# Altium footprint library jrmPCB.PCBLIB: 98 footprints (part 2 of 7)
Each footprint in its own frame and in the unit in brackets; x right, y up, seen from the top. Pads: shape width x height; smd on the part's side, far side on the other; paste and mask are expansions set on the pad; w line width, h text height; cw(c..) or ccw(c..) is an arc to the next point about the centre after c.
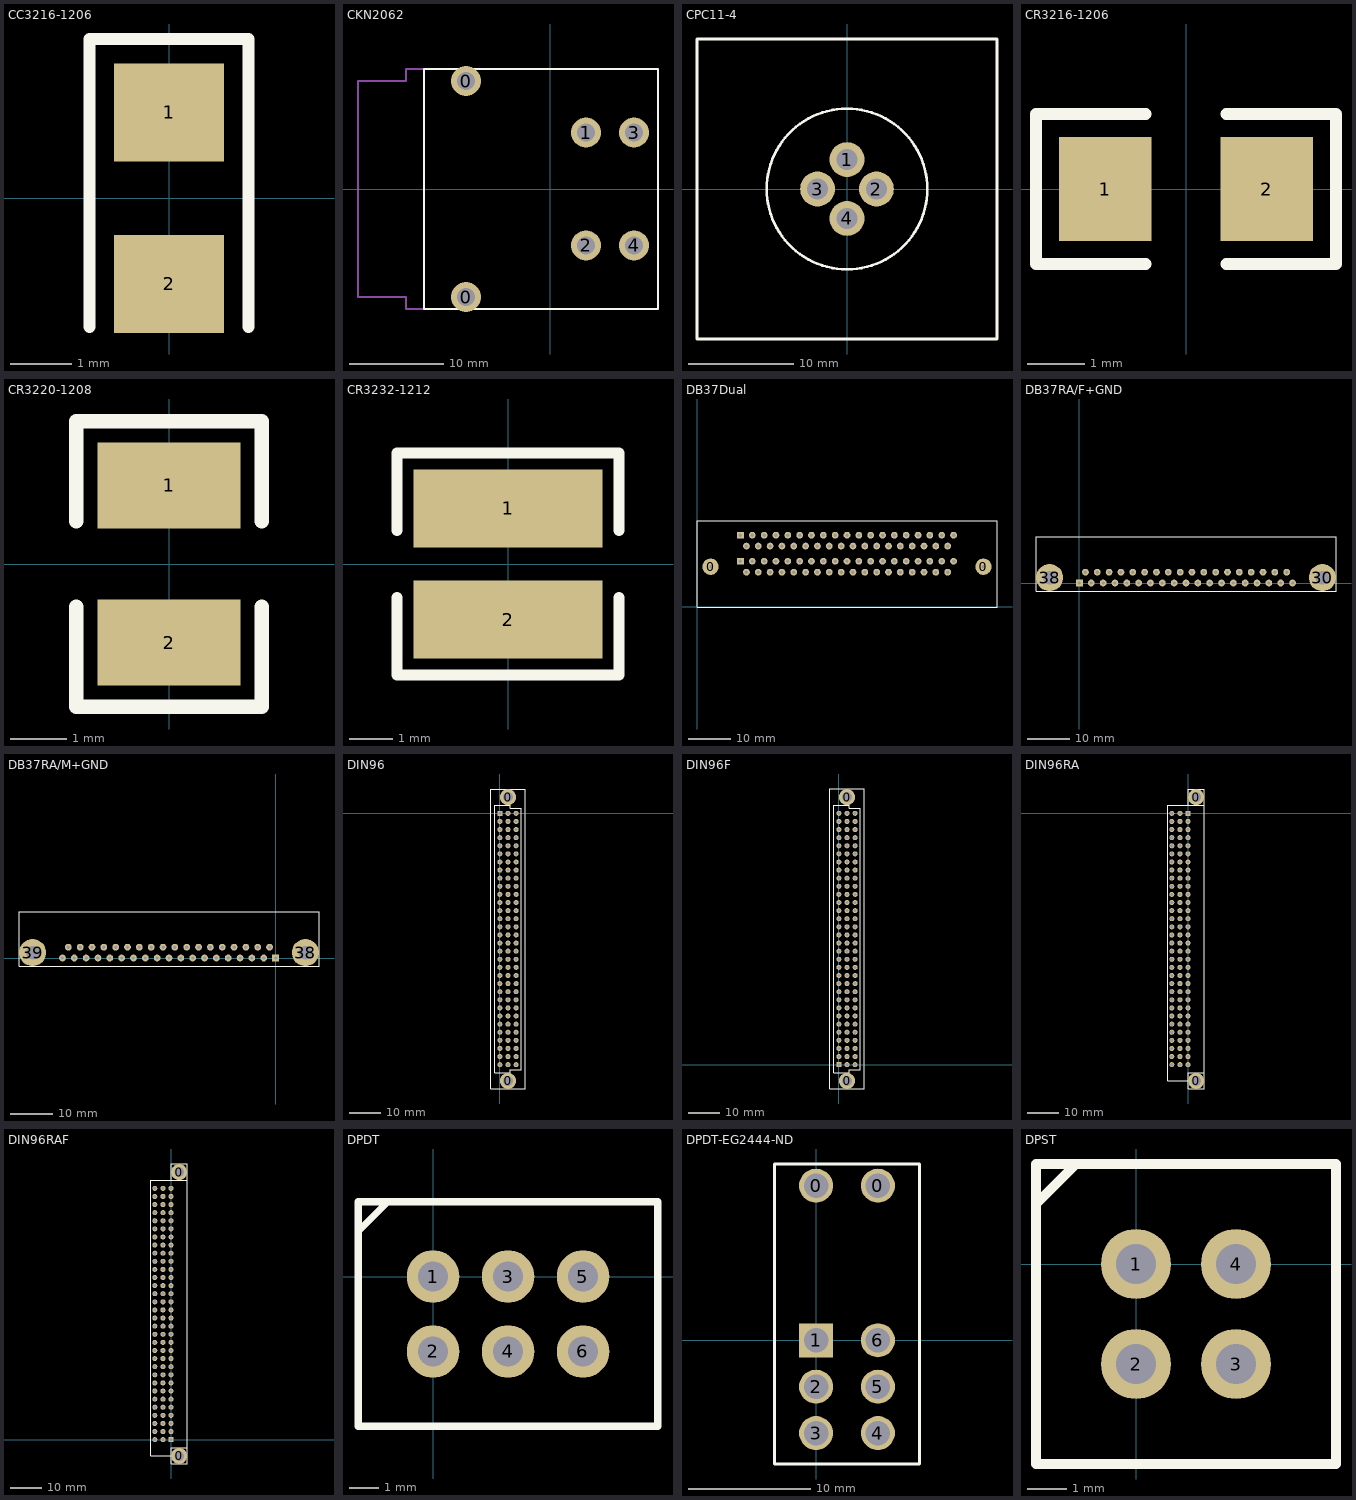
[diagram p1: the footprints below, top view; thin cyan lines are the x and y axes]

## CC3216-1206 [mm]
pads (2):
  rect 1.8x1.6 smd: 1(0,1.4) 2(0,-1.4)
Top Overlay:
  lines w0.2: -1.3,-2.1 -1.3,2.6 1.3,2.6 1.3,-2.1

## CKN2062 [mil] "DPST PCB Mount Rocker Switch"
pads (6):
  round 125 hole 75: 0(-350,-450) 0(-350,450) 1(150,235) 2(150,-235) 3(350,235) 4(350,-235)
Top Overlay:
  lines w10: -525,-500 -525,500 450,500 450,-500 -525,-500
Mechanical 2:
  lines w10: -525,-500 -600,-500 -600,-450 -800,-450 -800,450 -600,450 -600,500 -525,500

## CPC11-4 [mil] "PCB Mount for CPC 11-4 Solder Tab connector"
pads (4):
  round 130 hole 79: 1(0,110) 2(110,0) 3(-110,0) 4(0,-110)
Top Overlay:
  circle w10: c0,0 r300
  lines w10: -560,-560 560,-560 560,560 -560,560 -560,-560

## CR3216-1206 [mm]
pads (2):
  rect 1.6x1.8 smd: 1(-1.4,0) 2(1.4,0)
Top Overlay:
  lines w0.2: -0.7,-1.3 -2.6,-1.3 -2.6,1.3 -0.7,1.3 ; 0.7,-1.3 2.6,-1.3 2.6,1.3 0.7,1.3

## CR3220-1208 [mil]
pads (2):
  rect 100x60 smd: 1(0,55) 2(0,-55)
Top Overlay:
  lines w10: -65,-30 -65,-100 65,-100 65,-30 ; -65,30 -65,100 65,100 65,30

## CR3232-1212 [mil]
pads (2):
  rect 170x70 smd: 1(0,50) 2(0,-50)
Top Overlay:
  lines w10: -100,-30 -100,-100 100,-100 100,-30 ; -100,30 -100,100 100,100 100,30

## DB37Dual [mil]
pads (76):
  round 150 hole 32: 0(125,370) 0(2637,370)
  rect 62x62 hole 32: 1(400,420) 1(400,660.16)
  round 62 hole 32: 2(509,420) 2(509,660.16) 3(618,420) 3(618,660.16) 4(727,420) 4(727,660.16) 5(836,420) 5(836,660.16) 6(945,420) 6(945,660.16) 7(1054,420) 7(1054,660.16) 8(1163,420) 8(1163,660.16) 9(1272,420) 9(1272,660.16) 10(1381,420) 10(1381,660.16) 11(1490,420) 11(1490,660.16) 12(1599,420) 12(1599,660.16) 13(1708,420) 13(1708,660.16) 14(1817,420) 14(1817,660.16) 15(1926,420) 15(1926,660.16) 16(2035,420) 16(2035,660.16) 17(2144,420) 17(2144,660.16) 18(2253,420) 18(2253,660.16) 19(2362,420) 19(2362,660.16) 20(455,320) 20(455,560.16) 21(564,320) 21(564,560.16) 22(673,320) 22(673,560.16) 23(782,320) 23(782,560.16) 24(891,320) 24(891,560.16) 25(1000,320) 25(1000,560.16) 26(1109,320) 26(1109,560.16) 27(1218,320) 27(1218,560.16) 28(1327,320) 28(1327,560.16) 29(1436,320) 29(1436,560.16) 30(1545,320) 30(1545,560.16) 31(1654,320) 31(1654,560.16) 32(1763,320) 32(1763,560.16) 33(1872,320) 33(1872,560.16) 34(1981,320) 34(1981,560.16) 35(2090,320) 35(2090,560.16) 36(2199,320) 36(2199,560.16) 37(2308,320) 37(2308,560.16)
Top Overlay:
  lines w8: 0,795 2762,795 2762,-5
  lines w10: 0,795 0,-5 2762,-5

## DB37RA/F+GND [mil]
pads (39):
  rect 62x62 hole 32: 1(0,0)
  round 62 hole 32: 2(109,0) 3(218,0) 4(327,0) 5(436,0) 6(545,0) 7(654,0) 8(763,0) 9(872,0) 10(981,0) 11(1090,0) 12(1199,0) 13(1308,0) 14(1417,0) 15(1526,0) 16(1635,0) 17(1744,0) 18(1853,0) 19(1962,0) 20(55,100) 21(164,100) 22(273,100) 23(382,100) 24(491,100) 25(600,100) 26(709,100) 27(818,100) 28(927,100) 29(1036,100) 30(1145,100) 31(1254,100) 32(1363,100) 33(1472,100) 34(1581,100) 35(1690,100) 36(1799,100) 37(1908,100)
  round 250 hole 125: 30(2237,50) 38(-275,50)
Top Overlay:
  lines w8: -400,-75 2362,-75 2362,425
  lines w10: -400,-75 -400,425 2362,425

## DB37RA/M+GND [mil]
pads (39):
  rect 62x62 hole 32: 1(0,0)
  round 62 hole 32: 2(-109,0) 3(-218,0) 4(-327,0) 5(-436,0) 6(-545,0) 7(-654,0) 8(-763,0) 9(-872,0) 10(-981,0) 11(-1090,0) 12(-1199,0) 13(-1308,0) 14(-1417,0) 15(-1526,0) 16(-1635,0) 17(-1744,0) 18(-1853,0) 19(-1962,0) 20(-55,100) 21(-164,100) 22(-273,100) 23(-382,100) 24(-491,100) 25(-600,100) 26(-709,100) 27(-818,100) 28(-927,100) 29(-1036,100) 30(-1145,100) 31(-1254,100) 32(-1363,100) 33(-1472,100) 34(-1581,100) 35(-1690,100) 36(-1799,100) 37(-1908,100)
  round 250 hole 125: 38(275,50) 39(-2237,50)
Top Overlay:
  lines w8: -2362,425 -2362,-75 400,-75
  lines w10: -2362,425 400,425 400,-75

## DIN96 [mil]
pads (98):
  round 200 hole 125: 0(100,-3300) 0(100,200)
  rect 62x62 hole 40: 1A(0,0)
  round 62 hole 40: 1B(100,0) 1C(200,0) 2A(0,-100) 2B(100,-100) 2C(200,-100) 3A(0,-200) 3B(100,-200) 3C(200,-200) 4A(0,-300) 4B(100,-300) 4C(200,-300) 5A(0,-400) 5B(100,-400) 5C(200,-400) 6A(0,-500) 6B(100,-500) 6C(200,-500) 7A(0,-600) 7B(100,-600) 7C(200,-600) 8A(0,-700) 8B(100,-700) 8C(200,-700) 9A(0,-800) 9B(100,-800) 9C(200,-800) 10A(0,-900) 10B(100,-900) 10C(200,-900) 11A(0,-1000) 11B(100,-1000) 11C(200,-1000) 12A(0,-1100) 12B(100,-1100) 12C(200,-1100) 13A(0,-1200) 13B(100,-1200) 13C(200,-1200) 14A(0,-1300) 14B(100,-1300) 14C(200,-1300) 15A(0,-1400) 15B(100,-1400) 15C(200,-1400) 16A(0,-1500) 16B(100,-1500) 16C(200,-1500) 17A(0,-1600) 17B(100,-1600) 17C(200,-1600) 18A(0,-1700) 18B(100,-1700) 18C(200,-1700) 19A(0,-1800) 19B(100,-1800) 19C(200,-1800) 20A(0,-1900) 20B(100,-1900) 20C(200,-1900) 21A(0,-2000) 21B(100,-2000) 21C(200,-2000) 22A(0,-2100) 22B(100,-2100) 22C(200,-2100) 23A(0,-2200) 23B(100,-2200) 23C(200,-2200) 24A(0,-2300) 24B(100,-2300) 24C(200,-2300) 25A(0,-2400) 25B(100,-2400) 25C(200,-2400) 26A(0,-2500) 26B(100,-2500) 26C(200,-2500) 27A(0,-2600) 27B(100,-2600) 27C(200,-2600) 28A(0,-2700) 28B(100,-2700) 28C(200,-2700) 29A(0,-2800) 29B(100,-2800) 29C(200,-2800) 30A(0,-2900) 30B(100,-2900) 30C(200,-2900) 31A(0,-3000) 31B(100,-3000) 31C(200,-3000) 32A(0,-3100) 32B(100,-3100) 32C(200,-3100)
Top Overlay:
  lines w10: -110,-3400 310,-3400 310,300 -110,300 -110,-3400 ; -65,-3200 -65,100 130,100 130,65 265,65 265,-3165 130,-3165 130,-3200 -65,-3200

## DIN96F [mil]
pads (98):
  round 200 hole 125: 0(100,-200) 0(100,3300)
  rect 62x62 hole 40: 1A(0,0)
  round 62 hole 40: 1B(100,0) 1C(200,0) 2A(0,100) 2B(100,100) 2C(200,100) 3A(0,200) 3B(100,200) 3C(200,200) 4A(0,300) 4B(100,300) 4C(200,300) 5A(0,400) 5B(100,400) 5C(200,400) 6A(0,500) 6B(100,500) 6C(200,500) 7A(0,600) 7B(100,600) 7C(200,600) 8A(0,700) 8B(100,700) 8C(200,700) 9A(0,800) 9B(100,800) 9C(200,800) 10A(0,900) 10B(100,900) 10C(200,900) 11A(0,1000) 11B(100,1000) 11C(200,1000) 12A(0,1100) 12B(100,1100) 12C(200,1100) 13A(0,1200) 13B(100,1200) 13C(200,1200) 14A(0,1300) 14B(100,1300) 14C(200,1300) 15A(0,1400) 15B(100,1400) 15C(200,1400) 16A(0,1500) 16B(100,1500) 16C(200,1500) 17A(0,1600) 17B(100,1600) 17C(200,1600) 18A(0,1700) 18B(100,1700) 18C(200,1700) 19A(0,1800) 19B(100,1800) 19C(200,1800) 20A(0,1900) 20B(100,1900) 20C(200,1900) 21A(0,2000) 21B(100,2000) 21C(200,2000) 22A(0,2100) 22B(100,2100) 22C(200,2100) 23A(0,2200) 23B(100,2200) 23C(200,2200) 24A(0,2300) 24B(100,2300) 24C(200,2300) 25A(0,2400) 25B(100,2400) 25C(200,2400) 26A(0,2500) 26B(100,2500) 26C(200,2500) 27A(0,2600) 27B(100,2600) 27C(200,2600) 28A(0,2700) 28B(100,2700) 28C(200,2700) 29A(0,2800) 29B(100,2800) 29C(200,2800) 30A(0,2900) 30B(100,2900) 30C(200,2900) 31A(0,3000) 31B(100,3000) 31C(200,3000) 32A(0,3100) 32B(100,3100) 32C(200,3100)
Top Overlay:
  lines w10: 130,-65 265,-65 ; 130,-65 265,-65 ; 130,-65 130,-100 -65,-100 -65,3200 130,3200 130,3165 265,3165 265,-65 ; -110,-300 310,-300 310,3400 -110,3400 -110,-300

## DIN96RA [mil]
pads (98):
  round 200 hole 120: 0(100,-3300) 0(100,200)
  rect 62x62 hole 40: 1A(0,0)
  round 62 hole 40: 1B(-100,0) 1C(-200,0) 2A(0,-100) 2B(-100,-100) 2C(-200,-100) 3A(0,-200) 3B(-100,-200) 3C(-200,-200) 4A(0,-300) 4B(-100,-300) 4C(-200,-300) 5A(0,-400) 5B(-100,-400) 5C(-200,-400) 6A(0,-500) 6B(-100,-500) 6C(-200,-500) 7A(0,-600) 7B(-100,-600) 7C(-200,-600) 8A(0,-700) 8B(-100,-700) 8C(-200,-700) 9A(0,-800) 9B(-100,-800) 9C(-200,-800) 10A(0,-900) 10B(-100,-900) 10C(-200,-900) 11A(0,-1000) 11B(-100,-1000) 11C(-200,-1000) 12A(0,-1100) 12B(-100,-1100) 12C(-200,-1100) 13A(0,-1200) 13B(-100,-1200) 13C(-200,-1200) 14A(0,-1300) 14B(-100,-1300) 14C(-200,-1300) 15A(0,-1400) 15B(-100,-1400) 15C(-200,-1400) 16A(0,-1500) 16B(-100,-1500) 16C(-200,-1500) 17A(0,-1600) 17B(-100,-1600) 17C(-200,-1600) 18A(0,-1700) 18B(-100,-1700) 18C(-200,-1700) 19A(0,-1800) 19B(-100,-1800) 19C(-200,-1800) 20A(0,-1900) 20B(-100,-1900) 20C(-200,-1900) 21A(0,-2000) 21B(-100,-2000) 21C(-200,-2000) 22A(0,-2100) 22B(-100,-2100) 22C(-200,-2100) 23A(0,-2200) 23B(-100,-2200) 23C(-200,-2200) 24A(0,-2300) 24B(-100,-2300) 24C(-200,-2300) 25A(0,-2400) 25B(-100,-2400) 25C(-200,-2400) 26A(0,-2500) 26B(-100,-2500) 26C(-200,-2500) 27A(0,-2600) 27B(-100,-2600) 27C(-200,-2600) 28A(0,-2700) 28B(-100,-2700) 28C(-200,-2700) 29A(0,-2800) 29B(-100,-2800) 29C(-200,-2800) 30A(0,-2900) 30B(-100,-2900) 30C(-200,-2900) 31A(0,-3000) 31B(-100,-3000) 31C(-200,-3000) 32A(0,-3100) 32B(-100,-3100) 32C(-200,-3100)
Top Overlay:
  lines w9.84: 0,-3400 200,-3400 200,-3180 ; 0,-3200 200,-3200 ; 0,100 200,100 ; 0,300 200,300 200,80
  lines w10: 0,-3400 0,-3200 ; 0,-3300 -250,-3300 -250,100 0,100 0,300 ; 200,-3200 200,100

## DIN96RAF [mil]
pads (98):
  round 200 hole 120: 0(100,-200) 0(100,3300)
  rect 62x62 hole 40: 1A(0,0)
  round 62 hole 40: 1B(-100,0) 1C(-200,0) 2A(0,100) 2B(-100,100) 2C(-200,100) 3A(0,200) 3B(-100,200) 3C(-200,200) 4A(0,300) 4B(-100,300) 4C(-200,300) 5A(0,400) 5B(-100,400) 5C(-200,400) 6A(0,500) 6B(-100,500) 6C(-200,500) 7A(0,600) 7B(-100,600) 7C(-200,600) 8A(0,700) 8B(-100,700) 8C(-200,700) 9A(0,800) 9B(-100,800) 9C(-200,800) 10A(0,900) 10B(-100,900) 10C(-200,900) 11A(0,1000) 11B(-100,1000) 11C(-200,1000) 12A(0,1100) 12B(-100,1100) 12C(-200,1100) 13A(0,1200) 13B(-100,1200) 13C(-200,1200) 14A(0,1300) 14B(-100,1300) 14C(-200,1300) 15A(0,1400) 15B(-100,1400) 15C(-200,1400) 16A(0,1500) 16B(-100,1500) 16C(-200,1500) 17A(0,1600) 17B(-100,1600) 17C(-200,1600) 18A(0,1700) 18B(-100,1700) 18C(-200,1700) 19A(0,1800) 19B(-100,1800) 19C(-200,1800) 20A(0,1900) 20B(-100,1900) 20C(-200,1900) 21A(0,2000) 21B(-100,2000) 21C(-200,2000) 22A(0,2100) 22B(-100,2100) 22C(-200,2100) 23A(0,2200) 23B(-100,2200) 23C(-200,2200) 24A(0,2300) 24B(-100,2300) 24C(-200,2300) 25A(0,2400) 25B(-100,2400) 25C(-200,2400) 26A(0,2500) 26B(-100,2500) 26C(-200,2500) 27A(0,2600) 27B(-100,2600) 27C(-200,2600) 28A(0,2700) 28B(-100,2700) 28C(-200,2700) 29A(0,2800) 29B(-100,2800) 29C(-200,2800) 30A(0,2900) 30B(-100,2900) 30C(-200,2900) 31A(0,3000) 31B(-100,3000) 31C(-200,3000) 32A(0,3100) 32B(-100,3100) 32C(-200,3100)
Top Overlay:
  lines w9.84: 0,-300 200,-300 200,-80 ; 0,-100 200,-100 ; 0,3200 200,3200 ; 0,3400 200,3400 200,3180
  lines w10: 0,-300 0,-100 ; 0,-200 -250,-200 -250,3200 0,3200 0,3400 ; 200,-100 200,3200

## DPDT [mil]
pads (6):
  round 70 hole 40: 1(0,0) 2(0,-100) 3(100,0) 4(100,-100) 5(200,0) 6(200,-100)
Top Overlay:
  lines w10: -100,60 -60,100 ; -100,-200 300,-200 300,100 -100,100 -100,-200

## DPDT-EG2444-ND [mil] "DPDT Switch, RA PCB Mount"
pads (8):
  round 110 hole 79: 0(0,500) 0(200,500) 2(0,-150) 3(0,-300) 4(200,-300) 5(200,-150) 6(200,0)
  rect 110x110 hole 79: 1(0,0)
Top Overlay:
  lines w10: -134,-400 -134,570 334,570 334,-400 -134,-400

## DPST [mil]
pads (4):
  round 70 hole 40: 1(0,0) 2(0,-100) 3(100,-100) 4(100,0)
Top Overlay:
  lines w10: -100,60 -60,100 ; -100,-200 -100,100 200,100 200,-200 -100,-200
